(* Logix 5000 project; controller logix5561 vendor 1 type 14 code 54 rev 19.11; software revision 19.01 *)

TASK MainTask (continuous, watchdog 500 ms) : MainProgram

MODULES
   Local : vendor 1 type 14 code 54 (ICP 0, rev 19.11)
      eipscanner : 1756-ENBT (ICP 1, Ethernet 192.168.16.199, rev 6.1)
         Toshiba_Inverter : ETHERNET-MODULE (Ethernet 192.168.16.22, rev 1.1, Output RPI 10 ms)
END_MODULES

ADD_ON_INSTRUCTION ASDG9ETH_Generic_Default_IO   (* revision 1.0 *)
// Simple interface for generic default IO mapping that uses Input Assembly Instance 150 and Output Assembly Instance 100.
VAR_IN_OUT
   I_Data : INT[2]; {required}   // Input data
   O_Data : INT[2]; {required}   // Output data
END_VAR
VAR_INPUT
   FwdRev : BOOL; {access Read Only, required}   // Forward (0) or Reverse (1) direction
   RunStop : BOOL; {access Read Only, required}   // Run (1) or Stop (0)
   FaultReset : BOOL; {required}   // Reset the fault
   FreqPrioritySel : BOOL; {required}   // Frequency priority selection
   CmdPrioritySel : BOOL; {required}   // Command priority selection
   FrequencyCommand : INT; {access Read Only, required}   // Frequency command/reference
END_VAR
VAR_OUTPUT
   Alarm : BOOL; {access Read Only, visible}   // Alarm or Trip
   RunningFwdRev : BOOL; {access Read Only, visible}   // Running forward (0) or reverse (1)
   RunningStopped : BOOL; {access Read Only, visible}   // Running (1) or Stopped (0)
   EStop : BOOL; {access Read Only, visible}   // Emergency stop
   Standby : BOOL; {access Read Only, visible}   // Startup process (0) or Standby (1)
   OutputFrequency : INT; {access Read Only, visible}   // Output/feedback frequency
END_VAR

ROUTINE Logic   (* ladder *)
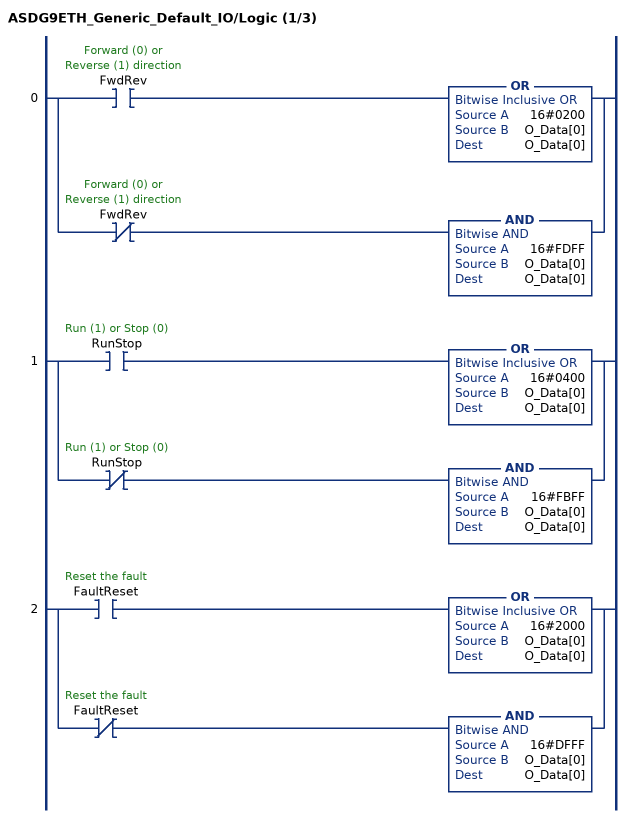
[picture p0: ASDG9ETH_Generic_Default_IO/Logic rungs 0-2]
   0: [XIC(FwdRev) OR(16#0200,O_Data[0],O_Data[0]) ,XIO(FwdRev) AND(16#FDFF,O_Data[0],O_Data[0]) ];
   1: [XIC(RunStop) OR(16#0400,O_Data[0],O_Data[0]) ,XIO(RunStop) AND(16#FBFF,O_Data[0],O_Data[0]) ];
   2: [XIC(FaultReset) OR(16#2000,O_Data[0],O_Data[0]) ,XIO(FaultReset) AND(16#DFFF,O_Data[0],O_Data[0]) ];
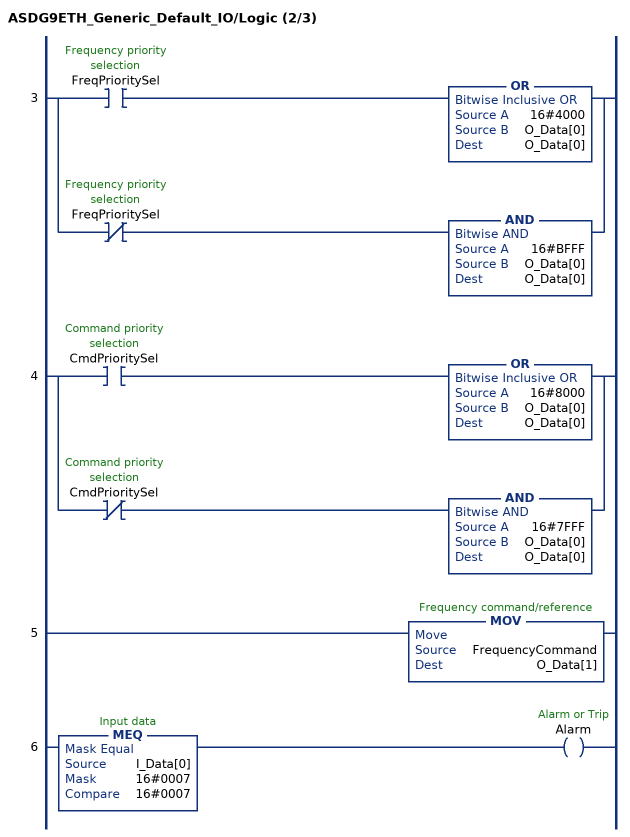
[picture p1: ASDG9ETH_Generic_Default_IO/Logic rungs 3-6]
   3: [XIC(FreqPrioritySel) OR(16#4000,O_Data[0],O_Data[0]) ,XIO(FreqPrioritySel) AND(16#BFFF,O_Data[0],O_Data[0]) ];
   4: [XIC(CmdPrioritySel) OR(16#8000,O_Data[0],O_Data[0]) ,XIO(CmdPrioritySel) AND(16#7FFF,O_Data[0],O_Data[0]) ];
   5: MOV(FrequencyCommand,O_Data[1]);
   6: MEQ(I_Data[0],16#0007,16#0007)OTE(Alarm);
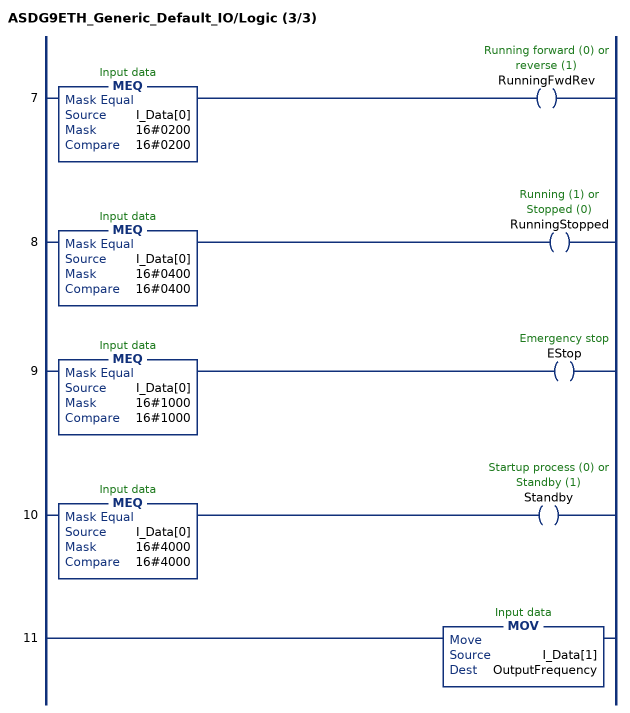
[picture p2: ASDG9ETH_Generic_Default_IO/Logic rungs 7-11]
   7: MEQ(I_Data[0],16#0200,16#0200)OTE(RunningFwdRev);
   8: MEQ(I_Data[0],16#0400,16#0400)OTE(RunningStopped);
   9: MEQ(I_Data[0],16#1000,16#1000)OTE(EStop);
   10: MEQ(I_Data[0],16#4000,16#4000)OTE(Standby);
   11: MOV(I_Data[1],OutputFrequency);
END_ROUTINE
END_ADD_ON_INSTRUCTION

VAR_GLOBAL   (* controller tags *)
   cmd_priority : BOOL;
   freq_cmd : INT;
   freq_priority : BOOL;
   fwd_rev : BOOL;
   generic_aoi : ASDG9ETH_Generic_Default_IO;
   reset : BOOL;
   run_stop : BOOL;
END_VAR

PROGRAM MainProgram   (* main routine MainRoutine *)

ROUTINE MainRoutine   (* ladder *)
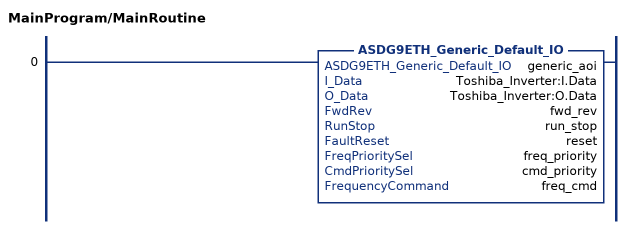
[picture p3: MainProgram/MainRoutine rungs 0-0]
   0: ASDG9ETH_Generic_Default_IO(generic_aoi,Toshiba_Inverter:I.Data,Toshiba_Inverter:O.Data,fwd_rev,run_stop,reset,freq_priority,cmd_priority,freq_cmd);
END_ROUTINE
END_PROGRAM
